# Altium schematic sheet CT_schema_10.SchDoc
size 308 x 210 mm
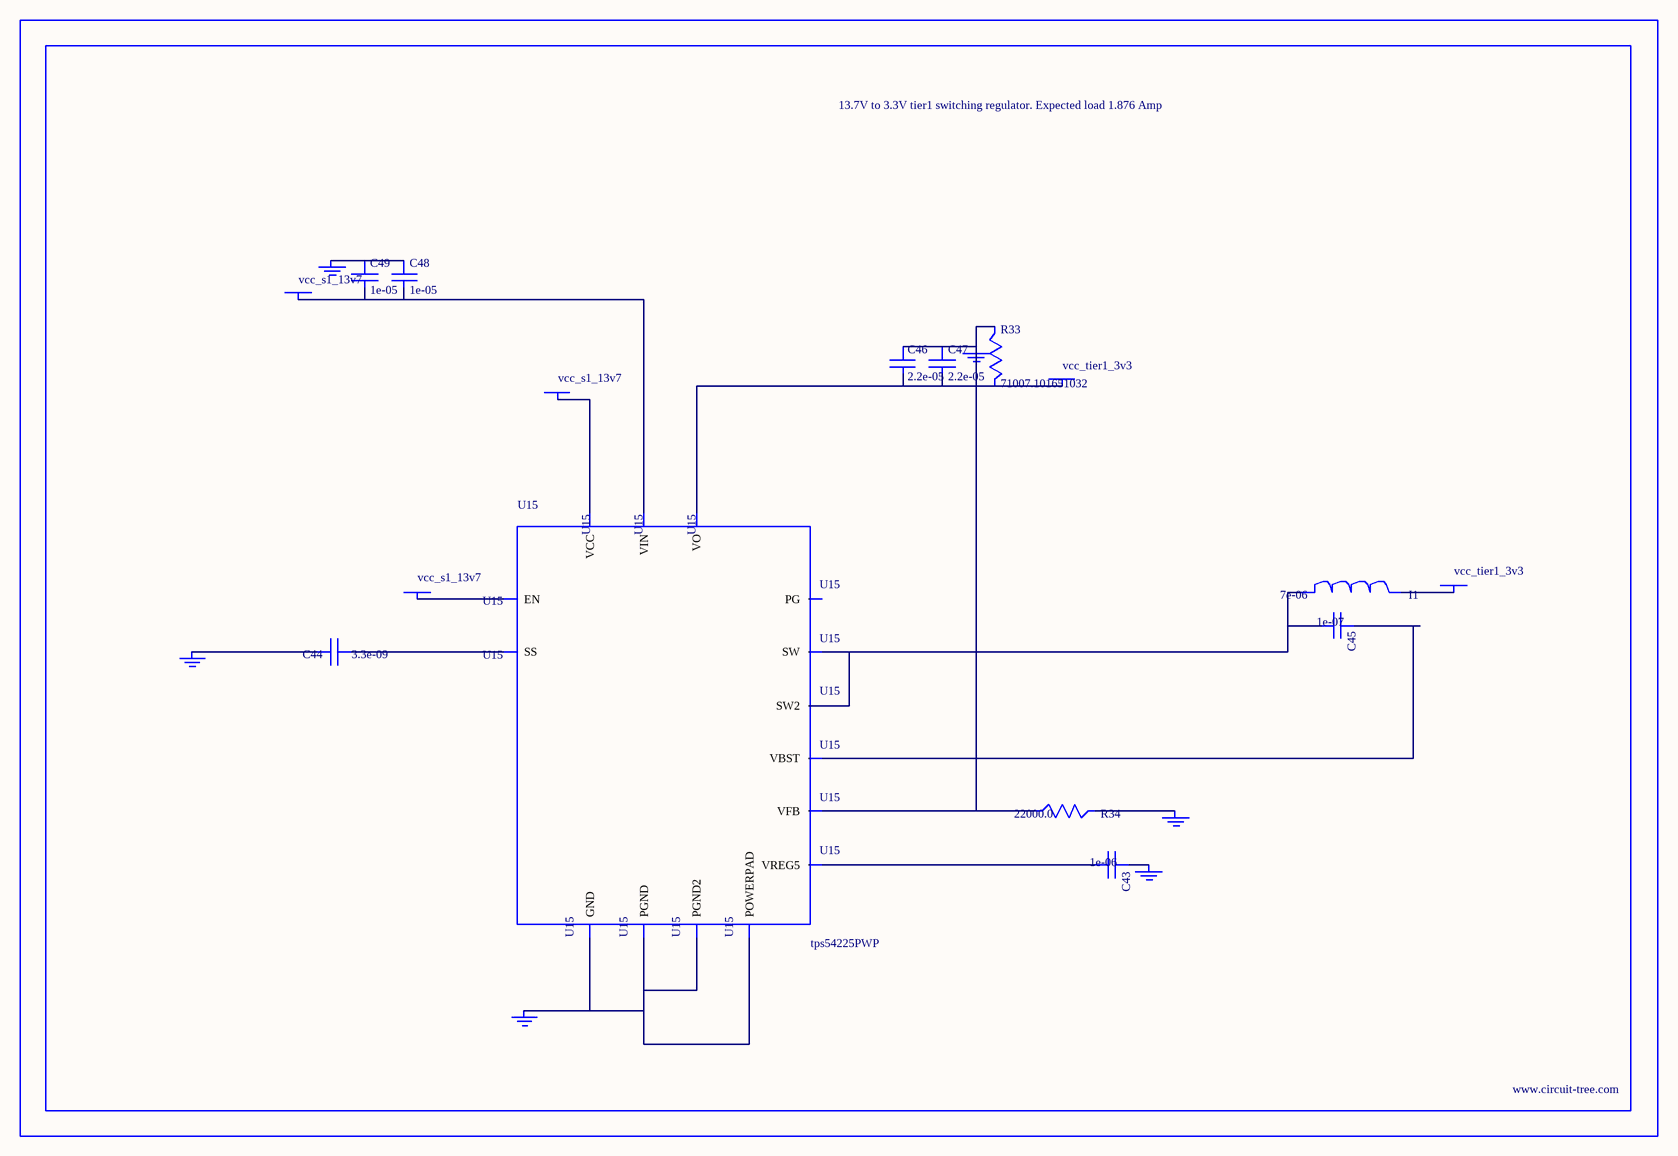
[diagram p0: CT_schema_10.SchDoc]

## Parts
BORDER9  (no value)
C43  1e-06  [C0603]
C44  3.3e-09  [C0402]
C45  1e-07  [C0402]
C46  2.2e-05  [C1210]
C47  2.2e-05  [C1210]
C48  1e-05  [C1206]
C49  1e-05  [C1206]
GND_INSTANCE_9_0  (no value)
GND_INSTANCE_9_1  (no value)
GND_INSTANCE_9_2  (no value)
GND_INSTANCE_9_3  (no value)
GND_INSTANCE_9_4  (no value)
GND_INSTANCE_9_5  (no value)
I1  7e-06  [DR1040]
POWER_INSTANCE_9_0  vcc_tier1_3v3
POWER_INSTANCE_9_1  vcc_s1_13v7
POWER_INSTANCE_9_2  vcc_tier1_3v3
POWER_INSTANCE_9_3  vcc_s1_13v7
POWER_INSTANCE_9_4  vcc_s1_13v7
R33  71007.101651032  [R0603]
R34  22000.0  [R0603]
U15  tps54225PWP  [HTSSOP14]

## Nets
NetC43_1: C43.1 GND_INSTANCE_9_2.0(GND)
NetC43_2: C43.2 U15.3(VREG5)
NetC44_1: C44.1 U15.4(SS)
NetC44_2: C44.2 GND_INSTANCE_9_3.0(GND)
NetC45_1: C45.1 U15.12(VBST)
NetC45_2: C45.2 I1.1 U15.10(SW) U15.11(SW2)
NetC46_1: C46.1 C47.1 GND_INSTANCE_9_0.0(GND) R33.1 R34.1 U15.2(VFB)
NetC46_2: C46.2 C47.2 POWER_INSTANCE_9_0.0(PWR) R33.2 U15.1(VO)
NetC48_1: C48.1 C49.1 GND_INSTANCE_9_5.0(GND)
NetC48_2: C48.2 C49.2 POWER_INSTANCE_9_3.0(PWR) U15.13(VIN)
NetGND_INSTANCE_9_1_0: GND_INSTANCE_9_1.0(GND) R34.2
NetGND_INSTANCE_9_4_0: GND_INSTANCE_9_4.0(GND) U15.5(GND) U15.8(PGND) U15.9(PGND2) U15.15(POWERPAD)
NetI1_2: I1.2 POWER_INSTANCE_9_2.0(PWR)
NetPOWER_INSTANCE_9_1_0: POWER_INSTANCE_9_1.0(PWR) U15.7(EN)
NetPOWER_INSTANCE_9_4_0: POWER_INSTANCE_9_4.0(PWR) U15.14(VCC)

Not connected (* = marked no-connect by the designer): U15 6(PG)

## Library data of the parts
BORDER9 = BORDER_PAGE9
C43 = C0603C105K3RACTU
C44 = C0402C332K3RAC
C45 = C0402C104K3RACTU
C46 C47 = GRM32ER61E226ME15L
C48 C49 = C1206C106K3RACTU
GND_INSTANCE_9_0-GND_INSTANCE_9_5 = GND
I1 = DR1040-7R0-R
POWER_INSTANCE_9_0-POWER_INSTANCE_9_4 = PWR
R33 = R33
R34 = RC0603JR-0722KL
